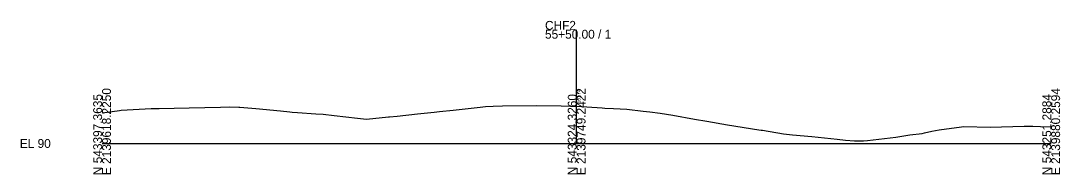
# Model space of a CAD drawing. Extents: x -12831 to 2303, y -10 to 39065.
# Drawn here: x 1974.3 to 2302.8, y 10990.3 to 11038.7 of the extents above; entities that cross this region are included whole.
import ezdxf

# ---------------------------------------------------------------- set-up
doc = ezdxf.new("R2010")
doc.units = 0
for name, color, linetype in [('RD_GPK_XS_Cell', 7, 'Continuous'), ('RD_XS_ExGround', 7, 'Continuous'), ('RD_XS_TX_Elev_EX', 7, 'Continuous')]:
    doc.layers.add(name, color=color, linetype=linetype)

msp = doc.modelspace()

# ---------------------------------------------------------------- linework, layer by layer
at = {"layer": 'RD_GPK_XS_Cell'}
for p, q in [((2150, 11000), (2150, 11035.88)), ((2000, 11000), (2150, 11000)), ((2150, 11000), (2300, 11000))]:
    msp.add_line(p, q, dxfattribs=at)
at = {"layer": 'RD_XS_ExGround'}
for p, q in [((2000, 11009.71), (2003.16, 11010.08)), ((2003.16, 11010.08), (2005.46, 11010.41)), ((2005.46, 11010.41), (2006.05, 11010.48)), ((2006.05, 11010.48), (2015.55, 11011.02)), ((2015.55, 11011.02), (2018.04, 11011.07)), ((2018.04, 11011.07), (2027.53, 11011.26)), ((2027.53, 11011.26), (2037.4, 11011.51)), ((2037.4, 11011.51), (2040.27, 11011.59)), ((2040.27, 11011.59), (2043.27, 11011.44)), ((2043.27, 11011.44), (2043.59, 11011.43)), ((2043.59, 11011.43), (2044.76, 11011.33)), ((2044.76, 11011.33), (2048.56, 11011.01)), ((2048.56, 11011.01), (2056.41, 11010.27)), ((2056.41, 11010.27), (2059.31, 11009.98)), ((2059.31, 11009.98), (2060.12, 11009.92)), ((2060.12, 11009.92), (2061.81, 11009.77)), ((2061.81, 11009.77), (2067.53, 11009.4)), ((2067.53, 11009.4), (2069.93, 11009.23)), ((2069.93, 11009.23), (2073.39, 11008.82)), ((2093.23, 11008.66), (2099.67, 11009.4)), ((2099.67, 11009.4), (2102.9, 11009.7)), ((2102.9, 11009.7), (2104.99, 11009.9)), ((2104.99, 11009.9), (2106.63, 11010.06)), ((2106.63, 11010.06), (2110.99, 11010.54)), ((2110.99, 11010.54), (2112.83, 11010.71)), ((2112.83, 11010.71), (2119.49, 11011.5)), ((2119.49, 11011.5), (2121.16, 11011.69)), ((2121.16, 11011.69), (2123.63, 11011.79)), ((2123.63, 11011.79), (2126.61, 11011.83)), ((2126.61, 11011.83), (2137.28, 11011.96)), ((2137.28, 11011.96), (2145.06, 11011.86)), ((2145.06, 11011.86), (2148.02, 11011.82)), ((2148.02, 11011.82), (2149.08, 11011.8)), ((2149.08, 11011.8), (2150, 11011.74)), ((2150, 11011.74), (2158.08, 11011.22)), ((2158.08, 11011.22), (2158.92, 11011.17)), ((2158.92, 11011.17), (2161.61, 11011)), ((2161.61, 11011), (2165.87, 11010.8)), ((2165.87, 11010.8), (2171.04, 11010.18)), ((2171.04, 11010.18), (2173.14, 11009.94)), ((2173.14, 11009.94), (2176.4, 11009.57)), ((2176.4, 11009.57), (2180.41, 11008.91)), ((2073.39, 11008.82), (2080.74, 11007.95)), ((2080.74, 11007.95), (2082.63, 11007.77)), ((2082.63, 11007.77), (2083.56, 11007.67)), ((2083.56, 11007.67), (2090.51, 11008.36)), ((2090.51, 11008.36), (2090.88, 11008.39)), ((2090.88, 11008.39), (2093.23, 11008.66)), ((2180.41, 11008.91), (2187.28, 11007.7)), ((2187.28, 11007.7), (2191.1, 11007.07)), ((2191.1, 11007.07), (2197.69, 11005.92)), ((2197.69, 11005.92), (2207.62, 11004.33)), ((2207.62, 11004.33), (2208.3, 11004.22)), ((2208.3, 11004.22), (2208.71, 11004.15)), ((2208.71, 11004.15), (2215.35, 11003.05)), ((2215.35, 11003.05), (2218.18, 11002.76)), ((2218.18, 11002.76), (2224.37, 11002.15)), ((2250.84, 11002.02), (2255.33, 11002.7)), ((2255.33, 11002.7), (2259.18, 11003.16)), ((2259.18, 11003.16), (2259.99, 11003.4)), ((2259.99, 11003.4), (2262.27, 11003.93)), ((2262.27, 11003.93), (2264.54, 11004.31)), ((2264.54, 11004.31), (2271.66, 11005.3)), ((2271.66, 11005.3), (2272.39, 11005.32)), ((2272.39, 11005.32), (2280.73, 11005.14)), ((2280.73, 11005.14), (2291.49, 11005.47)), ((2291.49, 11005.47), (2293.3, 11005.48)), ((2293.3, 11005.48), (2294.19, 11005.51)), ((2294.19, 11005.51), (2296.65, 11005.4)), ((2296.65, 11005.4), (2300, 11005.27)), ((2224.37, 11002.15), (2232.3, 11001.36)), ((2232.3, 11001.36), (2234.95, 11001.06)), ((2234.95, 11001.06), (2237.81, 11000.83)), ((2237.81, 11000.83), (2238.25, 11000.81)), ((2238.25, 11000.81), (2239.58, 11000.87)), ((2239.58, 11000.87), (2240.69, 11000.81)), ((2240.69, 11000.81), (2241.9, 11000.97)), ((2241.9, 11000.97), (2250.84, 11002.02))]:
    msp.add_line(p, q, dxfattribs=at)

# ---------------------------------------------------------------- texts
at = {"layer": 'RD_GPK_XS_Cell'}
for s, p in [('CHF2', (2140, 11035.88)), ('55+50.00 / 1', (2140, 11033.08)), ('EL 90', (1974, 10998.6))]:
    msp.add_text(s, height=2.8, dxfattribs=at).set_placement(p)
for s, p in [('E 2139618.2250', (2002.8, 10990)), ('E 2139749.2422', (2152.8, 10990)), ('E 2139880.2594', (2302.8, 10990)), ('N 543397.3635', (2000, 10990)), ('N 543324.3260', (2150, 10990)), ('N 543251.2884', (2300, 10990))]:
    msp.add_text(s, height=2.8, rotation=90, dxfattribs=at).set_placement(p)
at = {"layer": 'RD_XS_TX_Elev_EX'}
msp.add_text('101.74', height=1, rotation=90, dxfattribs=at).set_placement((2151.25, 11012.74))

doc.saveas('drawing.dxf')
